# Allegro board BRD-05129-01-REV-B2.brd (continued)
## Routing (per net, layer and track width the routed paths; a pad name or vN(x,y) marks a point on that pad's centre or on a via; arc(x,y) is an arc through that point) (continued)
HPA09P: length 124.6
  TOP w0.094: JA1.D10 v4(12.65,46.94)
  L03_SIG w0.102: v1(103.93,78.84) 103.93,78.28 103.01,77.35 102.17,77.35 101.1,76.28 101.1,75.8 99.82,74.52 94.23,74.52 93.83,74.92 91.41,74.92 88.26,78.07 88.26,79.14 86.81,80.59 86.21,80.59 83.24,77.61 74.06,77.61 70.02,73.57 70.02,73.27 65.43,68.68 53.11,68.68 50.74,66.31 50.74,58.79 48.93,56.98 48.17,56.98 44.89,53.71 27.19,53.71 19.58,46.1 14.42,46.1 14.04,46.48 13.11,46.48 v4(12.65,46.94)
  BOTTOM w0.13: v1(103.93,78.84) 103.93,79.24 R584.1 103.47,80.17 103.37,80.26 102.76,80.26 102.59,80.43 R570.2 102.59,81.4 101.77,82.22 100.7,82.22 100.27,82.64 100.27,83.66 100.03,83.9 U99.30
HPA10_CCN: length 134.4
  TOP w0.094: JA1.C13 v3(14.34,49.39)
  L03_SIG w0.102: v1(19.58,50.59) 17.85,50.59 17.34,50.08 15.03,50.08 v3(14.34,49.39)
  L05_SIG w0.102: v1(31.52,50.59) v1(19.58,50.59)
  L12_SIG w0.102: v1(31.52,50.59) 31.52,49.81 31.64,49.68 34.84,49.68 34.97,49.81 34.97,51.63 34.82,51.77 33.16,51.77 33.02,51.92 33.02,52.13 33.16,52.28 34.82,52.28 34.97,52.43 34.97,53.73 36.46,55.22 36.75,55.22 38.32,56.8 38.32,58.95 39.47,60.09 39.47,61.87 43.24,65.64 50.27,65.64 51.05,66.42 64.49,66.42 72.99,74.92 89.21,74.92 90.2,73.93 95.22,73.93 95.98,74.69 95.98,75.26 96.31,75.59 99.89,75.59 101.11,74.37 104.62,74.37 106.93,76.68 106.93,84.3 106.55,84.68 105.41,84.68 v1(101.55,88.54)
  BOTTOM w0.13: R563.2 102.09,88.82 101.82,88.82 v1(101.55,88.54) 101.24,88.24 101.24,87.86 100.96,87.57 100.7,87.57 100.03,86.9 U99.24
HPA10_CCP_CLK: length 133.1
  TOP w0.094: v3(14.34,48.75) 14.29,48.76 JA1.C12
  L03_SIG w0.102: v1(77.83,86.22) 76.83,85.21 72.01,85.21 71.78,84.98 71.78,83.18 71.07,82.47 69,82.47 67.78,81.25 66.83,81.25 63.64,78.06 62.28,78.06 62.04,78.3 60.04,78.3 59.3,79.04 54.08,79.04 52.83,77.8 52.52,77.8 51.84,77.11 50.5,77.11 49.08,75.69 49.08,74.35 44.92,70.19 43.65,70.19 33.74,60.28 32.49,60.28 32.34,60.13 32.34,58.2 32.19,58.05 31.98,58.05 31.83,58.2 31.83,60.13 31.69,60.28 31.48,60.28 31.33,60.13 31.33,58.2 31.18,58.05 30.97,58.05 30.82,58.2 30.82,60.13 30.67,60.28 30.46,60.28 30.31,60.13 30.31,58.2 30.16,58.05 29.95,58.05 29.8,58.2 29.8,60.13 29.65,60.28 29.44,60.28 29.29,60.13 29.29,58.2 29.15,58.05 28.94,58.05 28.79,58.2 28.79,60.13 28.64,60.28 28.43,60.28 28.28,60.13 28.28,58.2 28.13,58.05 27.92,58.05 27.77,58.2 27.77,60.13 27.62,60.28 26.91,60.28 18.63,52 15.07,52 14.7,51.63 14.7,50.47 13.86,49.63 13.86,49.23 v3(14.34,48.75)
  L05_SIG w0.102: v1(77.83,86.22) 77.83,87.07 82.2,91.44 94.56,91.44 97,89 99.82,89 v1(100.76,88.06)
  BOTTOM w0.13: U99.23 100.1,87.4 100.57,87.88 100.58,87.88 v1(100.76,88.06)
HPA11N: length 28.7
  TOP w0.094: JA1.B11 v4(15.19,47.57)
  L10_SIG w0.102: v4(15.19,47.57) 15.67,48.06 18.64,48.06 27.91,38.79 29.32,38.79 31.01,37.11 35.38,37.11 v1(36.01,37.73)
  BOTTOM w0.13: U19.2 35.09,39.46 35.51,39.03 35.51,38.22 v1(36.01,37.73)
HPA11P_CLK: length 71.6
  TOP w0.094: JA1.B10 v4(15.19,46.94)
  L03_SIG w0.102: v4(15.19,46.94) 15.6,47.35 15.6,48 15.83,48.23 19.17,48.23 27.3,56.37 32.34,56.37 49.73,73.76 49.99,73.76 53.46,77.24 53.46,77.44 53.89,77.87 55.5,77.87 56.69,76.68 58.8,76.68 59.66,77.54 60.75,77.54 61.21,77.08 63.78,77.08 66.85,80.15 67.52,80.15 v1(69.2,81.83)
  BOTTOM w0.13: v1(69.2,81.83) R477.2
HPA11P_CLK_R: length 1.8
  BOTTOM w0.13: R477.1 U91.3
HPA12N: length 39.8
  TOP w0.094: JA1.A10 v4(16.93,47.53)
  L05_SIG w0.102: v4(16.93,47.53) 17.51,48.12 33.84,48.12 35.33,46.63 41.25,46.63 48.46,39.42 v1(50.16,39.42)
  BOTTOM w0.13: v1(50.16,39.42) 50.16,40.43 50.42,40.7 U115.13
HPA12P_CLK: length 38.8
  TOP w0.094: JA1.A9 v4(16.93,46.9)
  L05_SIG w0.102: v4(16.93,46.9) 30.74,46.9 31.58,46.06 40.22,46.06 46.27,40 v1(46.27,39.62)
  BOTTOM w0.13: v1(46.27,39.62) 48.14,41.49 50.54,41.49 50.55,41.5 U115.15
HPA13N: length 38.6
  TOP w0.094: JA1.A13 v4(16.83,49.39)
  L05_SIG w0.102: v1(49.21,40.62) 40.44,49.39 36.41,49.39 36.41,49.39 36.02,49.39 36.02,49.39 v4(16.83,49.39)
  BOTTOM w0.13: U115.14 50.56,41.1 50.55,41.11 49.69,41.11 v1(49.21,40.62)
HPA13P: length 39.6
  TOP w0.094: JA1.A12 v4(16.83,48.75)
  L05_SIG w0.102: v4(16.83,48.75) 33.89,48.75 34.55,48.09 40.67,48.09 48.74,40.03 50.83,40.03 v1(51.19,39.67)
  BOTTOM w0.13: U115.12 51.77,40.26 v1(51.19,39.67)
HPA14N: length 23.7
  TOP w0.094: JA1.D14 v4(12.65,49.48)
  L12_SIG w0.102: v4(12.65,49.48) 9.91,49.48 8.35,47.93 8.35,42.9 7.63,42.17 6.41,42.17 5.84,41.6 5.84,39.28 5.16,38.6 4.93,38.6 4.39,38.07 4.39,36.55 5.76,35.17 v1(5.76,34.59)
  BOTTOM w0.13: R474.1 5.45,34.9 v1(5.76,34.59) 5.35,34.18 Q23.1
HPA14P: length 18.1
  TOP w0.094: JA1.D13 v4(12.65,48.84)
  L12_SIG w0.102: v4(12.65,48.84) 9.95,48.84 8.99,47.88 8.99,42.52 8.36,41.88 8.36,41.01 v1(5.02,37.67)
  BOTTOM w0.13: v1(5.02,37.67) Q22.1 5.61,37.1 5.7,37.19 R473.1
HPA15_CCN: length 102.9
  TOP w0.127: v1(99.74,83.1) 99.54,83.3 U101.1
  TOP w0.13: JA3.C2 v4(45.17,58.28)
  L05_SIG w0.102: v1(99.74,83.1) 99.74,81.99 99.92,81.81 100.38,81.81 100.54,81.65 100.54,81.37 100.16,80.99 98.85,80.99 98.7,81.14 98.7,82.73 99.03,83.05 99.03,83.74 98.88,83.89 98.68,83.89 98.57,83.79 98.57,83.33 98.5,83.26 98.33,83.26 98.2,83.38 98.2,83.74 98.05,83.89 97.84,83.89 97.69,83.74 97.69,83.15 97.57,83.03 97.36,83.03 97.19,83.2 97.19,83.74 97.04,83.89 96.83,83.89 96.68,83.74 96.68,83.15 96.55,83.03 96.16,83.03 96.01,83.18 96.01,83.79 95.91,83.89 95.5,83.89 95.35,83.74 95.35,82.55 95.47,82.43 98.01,82.43 98.2,82.24 98.2,80.38 98.01,80.19 97.83,80.19 97.68,80.34 97.68,81.11 97.56,81.24 97.32,81.24 97.14,81.07 97.14,80.07 96.99,79.92 96.78,79.92 96.63,80.07 96.63,81.02 96.43,81.21 96.25,81.21 96.13,81.09 96.13,80.07 95.98,79.92 95.77,79.92 95.62,80.07 95.62,81.02 95.42,81.21 95.24,81.21 95.11,81.09 95.11,80.07 94.96,79.92 94.75,79.92 94.6,80.07 94.6,81.02 94.4,81.21 94.22,81.21 94.09,81.09 94.09,80.07 93.95,79.92 93.73,79.92 93.59,80.07 93.59,80.91 93.44,81.06 92.07,81.06 91.67,80.66 91.02,80.66 89.55,79.19 89.15,79.19 88.97,79.37 88.74,79.37 88.64,79.27 88.64,78.96 88.53,78.85 88.3,78.85 88.17,78.98 88.17,79.86 87.97,80.07 87.74,80.07 87.61,79.94 87.61,79.74 87.46,79.6 87.14,79.6 86.98,79.43 86.98,78.27 86.85,78.15 78.18,78.15 78,78.33 74.55,78.33 70.02,73.8 70.02,72.12 66.88,68.98 61.68,68.98 61.14,68.44 51.61,68.44 49.94,66.76 49.94,60.29 48.93,59.28 47.56,59.28 47.32,59.04 47.32,57.97 47.21,57.87 45.59,57.87 v4(45.17,58.28)
HPA15_CCP: length 104.9
  TOP w0.127: v1(100.63,76.09) 99.78,76.95 99.78,81.22 98.44,82.55 U101.39
  TOP w0.13: JA3.C1 v4(44.35,57.07)
  L05_SIG w0.102: v1(100.63,76.09) 100.63,75.38 99.77,74.52 93.09,74.52 91.77,75.84 91.08,75.84 90.93,75.69 90.93,75.13 90.78,74.98 90.57,74.98 90.42,75.13 90.42,75.69 90.27,75.84 90.06,75.84 89.91,75.69 89.91,75.13 89.76,74.98 89.55,74.98 89.4,75.13 89.4,75.69 89.25,75.84 89.04,75.84 88.9,75.69 88.9,75.13 88.75,74.98 88.54,74.98 88.39,75.13 88.39,75.69 88.24,75.84 88.03,75.84 87.88,75.69 87.88,75.13 87.73,74.98 87.52,74.98 87.37,75.13 87.37,75.69 87.22,75.84 87.01,75.84 86.86,75.69 86.86,75.13 86.71,74.98 86.5,74.98 86.36,75.13 86.36,75.69 86.21,75.84 86,75.84 85.85,75.69 85.85,75.13 85.7,74.98 85.49,74.98 85.34,75.13 85.34,75.69 85.19,75.84 84.98,75.84 84.83,75.69 84.83,75.13 84.68,74.98 84.47,74.98 84.32,75.13 84.32,75.69 84.17,75.84 83.96,75.84 83.82,75.69 83.82,75.13 83.67,74.98 83.46,74.98 83.31,75.13 83.31,75.69 83.16,75.84 82.95,75.84 82.8,75.69 82.8,75.13 82.65,74.98 82.44,74.98 82.29,75.13 82.29,75.69 82.14,75.84 81.93,75.84 81.78,75.69 81.78,75.13 81.63,74.98 81.42,74.98 81.28,75.13 81.28,75.69 81.13,75.84 80.92,75.84 80.77,75.69 80.77,75.13 80.62,74.98 80.41,74.98 80.26,75.13 80.26,75.69 80.11,75.84 79.9,75.84 79.75,75.69 79.75,75.13 79.6,74.98 79.39,74.98 79.24,75.13 79.24,75.69 79.09,75.84 78.88,75.84 78.74,75.69 78.74,75.13 78.59,74.98 78.38,74.98 78.23,75.13 78.23,75.69 78.08,75.84 77.87,75.84 77.72,75.69 77.72,75.13 77.57,74.98 77.36,74.98 77.21,75.13 77.21,75.69 77.06,75.84 76.85,75.84 76.7,75.69 76.7,75.13 76.55,74.98 76.34,74.98 76.2,75.13 76.2,75.69 76.05,75.84 75.69,75.84 72.72,72.86 72.72,70.62 68.12,66.03 53.95,66.03 53.02,65.1 53.02,59.7 49.65,56.34 49.65,54.91 48.87,54.12 44.6,54.12 43.58,55.14 43.58,56.31 v4(44.35,57.07)
HPA16N: length 103.9
  TOP w0.127: v1(98.22,75.08) 98.85,75.71 98.85,81.25 97.44,82.66 U101.37
  TOP w0.13: JA3.A2 v4(47.71,58.28)
  L05_SIG w0.102: v1(98.22,75.08) 98.73,75.59 98.73,76.07 98.88,76.22 98.96,76.22 99.11,76.37 99.11,76.58 98.96,76.73 98.88,76.73 98.73,76.88 98.73,77.32 98.88,77.47 99.69,77.47 99.9,77.27 100.11,77.27 100.25,77.42 100.25,77.63 100.05,77.83 100.05,78.04 100.32,78.3 103.2,78.3 103.65,77.85 104.22,77.85 104.77,78.41 108.1,78.41 108.23,78.53 108.23,78.84 108.16,79.01 108.05,79.12 104.42,79.12 104.11,79.42 102.97,79.42 102.82,79.57 102.82,80.41 102.67,80.56 102.46,80.56 102.31,80.41 102.31,78.94 102.19,78.82 101.92,78.82 101.82,78.91 101.82,79.32 101.72,79.42 101.29,79.42 100.78,79.93 100.5,79.93 99.93,79.36 99.93,79.19 100.08,79.04 100.08,78.87 99.96,78.75 99.79,78.75 99.64,78.9 99.47,78.9 99.01,78.44 98.78,78.44 98.65,78.31 98.65,77.97 98.5,77.82 98.24,77.82 98.04,78.02 98.04,78.3 97.91,78.44 94.11,78.44 93.56,77.89 91.1,77.89 90.07,76.86 77.61,76.86 77.11,77.36 75.17,77.36 71.27,73.46 71.27,71.35 67.39,67.48 53.17,67.48 51.47,65.77 51.47,60.29 48.94,57.76 47.84,57.76 47.71,57.88 v4(47.71,58.28)
HPA16P_CLK: length 105.1
  TOP w0.127: v4(48.74,58.24) 48.74,57.83 48.28,57.37 JA3.A1 ; U101.38 97.94,82.59 99.31,81.22 99.31,76.39 v1(99.61,76.09)
  L05_SIG w0.102: v4(48.74,58.24) 50.65,60.15 50.65,65.86 52.75,67.96 61.5,67.96 61.84,68.3 67.14,68.3 70.62,71.78 70.62,73.56 74.9,77.85 77.4,77.85 77.76,77.48 87.83,77.48 87.98,77.63 87.98,78.22 88.13,78.37 88.34,78.37 88.49,78.22 88.49,77.63 88.64,77.48 89.07,77.48 90.74,79.15 92.53,79.15 92.76,78.93 98.78,78.93 99.11,79.25 99.11,79.46 98.63,79.94 98.63,80.15 98.78,80.3 98.99,80.3 99.47,79.82 99.68,79.82 100.89,81.04 103.31,81.04 103.73,80.62 105.24,80.62 105.39,80.47 105.39,79.75 105.54,79.6 105.75,79.6 105.9,79.75 105.9,80.47 106.05,80.62 106.26,80.62 106.41,80.47 106.41,79.75 106.55,79.6 106.76,79.6 106.91,79.75 106.91,80.47 107.06,80.62 107.27,80.62 107.42,80.47 107.42,79.75 107.57,79.6 107.78,79.6 107.93,79.75 107.93,80.65 108.15,80.87 108.42,80.87 108.71,80.59 108.71,78.25 108.38,77.92 104.97,77.92 104.4,77.35 101.96,77.35 101.21,76.6 100.12,76.6 v1(99.61,76.09)
HPA17N: length 101.8
  TOP w0.127: U101.35 96.44,82.19 97.2,81.43 R597.2 97.71,80.51 97.71,79.21 R608.1 96.86,78.7 96.69,78.53 96.69,76.6 v1(97.2,76.09)
  TOP w0.13: JA3.D3 v4(43.53,58.37)
  L05_SIG w0.102: v1(97.2,76.09) 97.67,76.56 97.67,77.64 97.42,77.89 95.9,77.89 95.69,77.68 95.69,76.29 95.54,76.14 94.94,76.14 94.67,76.41 94.67,77.76 94.54,77.89 94.25,77.89 93.66,77.31 91.78,77.31 91.5,77.03 91.5,76.65 91.2,76.35 75.52,76.35 72.23,73.06 72.23,70.82 67.92,66.51 53.57,66.51 52.44,65.37 52.44,59.8 48.48,55.85 48.13,55.85 47.38,56.6 46.93,56.6 46.79,56.45 46.79,55.01 46.62,54.85 44.84,54.85 44.41,55.27 44.41,56.24 44.83,56.65 44.83,57.15 44.37,57.6 43.28,57.6 43.1,57.43 43.1,53.64 42.92,53.46 42.41,53.46 42.26,53.62 42.26,57.48 42.13,57.6 40.33,57.6 40.2,57.73 40.2,58.14 40.44,58.37 v4(43.53,58.37)
HPA17P: length 87.4
  TOP w0.127: Q33.1 80.53,96.67 R596.1 v1(81.33,96.57) ; U101.21 93.84,88.82 93.39,89.28 93.18,89.28 92.66,89.81 92.66,90.01 92.07,90.59 91.43,90.59 91.05,90.97 R605.2 R616.1 v1(91.05,92.63)
  TOP w0.13: JA3.D2 v4(44.36,58.3) ; v1(81.33,96.57) 81.33,96.13 81.96,95.5 81.96,92.71 79,89.75 79,79.36 v1(76.53,76.88)
  L05_SIG w0.102: v4(44.36,58.3) 45.18,57.48 46.25,57.48 46.48,57.25 49.17,57.25 51.95,60.03 51.95,65.57 53.37,66.99 67.72,66.99 71.75,71.02 71.75,73.26 75.37,76.88 v1(76.53,76.88)
  L10_SIG w0.102: v1(91.05,92.63) 90.39,91.97 87.35,91.97 82.75,96.57 v1(81.33,96.57)
HPA18N: length 99
  TOP w0.13: JA3.B3 v4(46.07,58.37) ; v1(93.14,78.38) 93.46,78.7 R611.1 93.65,79.21 93.65,80.82 93.82,80.99 R600.2 94.15,81.96 94.94,82.75 U101.32
  L03_SIG w0.102: v4(46.07,58.37) 46.45,58.75 46.45,59.36 46.71,59.61 47.09,59.61 47.32,59.84 47.32,61.06 48.27,62.01 48.27,65.33 48.12,65.48 47.76,65.48 47.61,65.63 47.61,65.84 47.76,65.99 48.12,65.99 48.27,66.14 48.27,66.35 48.12,66.5 47.76,66.5 47.61,66.64 47.61,66.86 47.76,67 48.12,67 48.27,67.15 48.27,67.82 51.79,71.34 51.79,72 52.78,73 54.45,73 55.24,72.21 56.65,72.21 56.79,72.36 56.79,73.53 56.94,73.68 57.15,73.68 57.3,73.53 57.3,72.36 57.45,72.21 57.66,72.21 57.81,72.36 57.81,73.53 57.96,73.68 58.17,73.68 58.32,73.53 58.32,72.36 58.47,72.21 60.25,72.21 60.4,72.36 60.4,72.92 60.55,73.07 60.76,73.07 60.91,72.92 60.91,72.36 61.06,72.21 61.27,72.21 61.42,72.36 61.42,72.92 61.57,73.07 61.78,73.07 61.92,72.92 61.92,72.36 62.07,72.21 62.28,72.21 62.43,72.36 62.43,72.92 62.58,73.07 62.79,73.07 62.94,72.92 62.94,72.36 63.09,72.21 63.64,72.21 65.33,73.91 66.71,73.91 72.83,80.03 74.75,80.03 77.21,82.49 88.28,82.49 88.81,81.96 90.24,81.96 91.05,82.78 92.86,82.78 94.5,84.42 94.5,86.48 94.75,86.73 94.9,86.73 95.09,86.54 95.09,84.69 95.34,84.44 96.01,84.44 96.11,84.34 96.11,83.61 96.01,83.5 94.88,83.5 94.61,83.24 94.61,82.44 93.46,81.29 92.25,81.29 91.91,80.95 91.91,80.3 92.53,79.68 92.53,78.99 v1(93.14,78.38)
HPA18P: length 99
  TOP w0.13: v1(94.15,76.09) 94.67,76.61 94.67,78.58 94.8,78.7 R612.1 94.66,79.21 94.66,80.82 94.83,80.99 R603.2 95.4,81.22 95.4,82.59 95.44,82.64 U101.33 ; JA3.B2 v4(46.9,58.3)
  L03_SIG w0.102: v1(94.15,76.09) 93.62,76.09 93.39,76.32 93.39,76.68 93.62,76.92 93.62,77.13 93.48,77.28 93.27,77.28 93.03,77.04 92.82,77.04 92.56,77.31 91.49,77.31 89.8,79 89.8,79.87 89.17,80.5 88.91,80.5 87.9,81.5 85.52,81.5 84.89,80.88 83.36,80.88 83.21,80.73 83.21,79.18 83.11,79.08 82.8,79.08 82.7,79.18 82.7,80.73 82.55,80.88 82.34,80.88 82.19,80.73 82.19,78.98 82.02,78.8 81.81,78.8 81.69,78.93 81.69,80.73 81.54,80.88 80.47,80.88 80.32,80.73 80.32,79.01 80.15,78.84 79.94,78.84 79.81,78.96 79.81,80.73 79.66,80.88 79.31,80.88 79.14,80.72 79.14,78.95 78.91,78.71 72.89,78.71 68.39,74.21 68.39,73.25 68.13,72.99 67.92,72.99 67.55,73.36 67.33,73.36 67.19,73.21 67.19,73 67.56,72.63 67.56,72.42 67.01,71.87 66.72,71.87 66.57,71.72 66.57,71.52 66.42,71.37 66.21,71.37 66.06,71.52 66.06,71.72 65.91,71.87 65.57,71.87 65.2,71.49 65.2,71.28 65.7,70.78 65.7,70.57 65.55,70.42 65.34,70.42 64.71,71.05 64.47,71.05 64.32,70.9 64.32,70.72 64.98,70.06 64.98,69.85 64.83,69.71 64.62,69.71 64.12,70.21 63.91,70.21 63.52,69.82 62.87,69.82 62.72,69.97 62.72,70.48 62.58,70.63 62.37,70.63 62.22,70.48 62.22,69.97 62.07,69.82 61.86,69.82 61.71,69.97 61.71,70.48 61.56,70.63 61.35,70.63 61.2,70.48 61.2,69.97 61.05,69.82 60.84,69.82 60.69,69.97 60.69,70.48 60.54,70.63 60.33,70.63 60.18,70.48 60.18,69.97 60.04,69.82 58.7,69.82 58.55,69.97 58.55,70.67 58.39,70.84 58.18,70.84 58.04,70.7 58.04,69.97 57.9,69.82 57.43,69.82 57.07,70.18 54.64,70.18 54.25,70.57 52.87,70.57 49.61,67.3 49.61,60.4 48.12,58.91 48.12,57.97 47.95,57.81 47.39,57.81 v4(46.9,58.3)
HPA19N: length 104.2
  TOP w0.127: U101.29 93.37,84.4 93.06,84.09 93.06,83.15 92.05,82.14 92.05,81.76 v1(91.74,81.45) R609.1 R598.2
  TOP w0.13: JA3.C5 v4(45.17,60.18)
  L05_SIG w0.102: v4(45.17,60.18) 44.8,59.81 42.92,59.81 42.8,59.69 42.8,59.46 42.87,59.38 45.64,59.38 45.77,59.51 48.1,59.51 49.26,60.67 49.26,66.77 51.41,68.92 54.43,68.92 54.57,69.07 54.57,69.44 54.72,69.59 54.93,69.59 55.08,69.44 55.08,69.07 55.23,68.92 56.64,68.92 56.79,69.07 56.79,69.47 56.93,69.62 57.14,69.62 57.29,69.47 57.29,69.07 57.44,68.92 59.51,68.92 59.51,68.93 60.81,68.93 61.44,69.56 66.62,69.56 69.53,72.47 69.53,74.67 69.78,74.91 69.99,74.91 70.11,74.79 70.32,74.79 70.47,74.94 70.47,75.15 70.35,75.27 70.35,75.48 70.49,75.63 70.7,75.63 70.83,75.51 71.04,75.51 71.19,75.65 71.19,75.86 71.06,75.99 71.06,76.2 71.21,76.35 71.42,76.35 71.55,76.22 71.76,76.22 71.91,76.37 71.91,76.58 71.78,76.71 71.78,76.92 71.93,77.07 72.14,77.07 72.27,76.94 72.48,76.94 72.62,77.09 72.62,77.3 72.5,77.42 72.5,77.64 72.65,77.78 72.86,77.78 72.98,77.66 73.19,77.66 73.34,77.81 73.34,78.02 73.22,78.14 73.22,78.35 73.68,78.81 77.51,78.81 77.66,78.96 77.66,80.21 77.81,80.36 78.02,80.36 78.17,80.21 78.17,78.96 78.32,78.81 80.19,78.81 80.32,78.68 81.68,78.68 81.83,78.83 81.83,78.97 81.97,79.12 82.18,79.12 82.33,78.97 82.33,78.83 82.48,78.68 82.69,78.68 82.84,78.83 82.84,78.97 82.99,79.12 83.2,79.12 83.35,78.97 83.35,78.83 83.5,78.68 83.71,78.68 83.86,78.83 83.86,78.97 84.01,79.12 84.22,79.12 84.37,78.97 84.37,78.83 84.51,78.68 85.03,78.68 85.8,79.46 85.8,80.22 86.13,80.55 86.82,80.55 86.96,80.7 86.96,81.69 87.11,81.84 87.32,81.84 87.47,81.69 87.47,80.7 87.62,80.55 87.83,80.55 87.98,80.7 87.98,81.69 88.13,81.84 88.34,81.84 88.49,81.69 88.49,80.7 88.64,80.55 89.16,80.55 89.56,80.96 89.77,80.96 90.09,80.63 90.3,80.63 90.45,80.78 90.45,80.99 90.13,81.31 90.13,81.52 90.28,81.67 90.49,81.67 90.81,81.35 91.02,81.35 91.17,81.5 91.17,81.71 90.85,82.03 90.85,82.24 91.1,82.49 91.31,82.49 91.59,82.2 91.8,82.2 91.95,82.35 91.95,82.56 91.66,82.85 91.66,83.06 91.89,83.29 91.89,83.76 92.23,84.1 92.66,84.1 93.51,84.95 94.13,84.95 94.64,84.44 94.64,84.03 94.49,83.88 93.38,83.88 93.23,83.73 93.23,83.52 93.38,83.37 94.49,83.37 94.64,83.22 94.64,82.37 94.14,81.88 93.43,81.88 93.28,82.03 93.28,82.78 93.13,82.93 92.92,82.93 92.77,82.78 92.77,82.03 92.62,81.88 92.16,81.88 v1(91.74,81.45)
HPA19P: length 104.4
  TOP w0.127: U101.30 93.61,83.9 93.39,83.69 93.39,82.83 92.43,81.86 92.43,80.62 v1(92.38,80.56) R610.1 R599.2
  TOP w0.13: JA3.C4 v4(44.35,58.98)
  L03_SIG w0.102: v4(44.35,58.98) 44.96,59.58 46.15,59.58 46.5,59.94 46.5,61.11 47.32,61.92 47.32,62.99 47.11,63.19 43.56,63.19 43.3,63.44 43.3,64.94 52.17,73.81 55.22,73.81 56.31,74.9 60.19,74.9 61.33,73.76 64.34,73.76 65.05,74.47 66.46,74.47 67,75.01 67,75.22 66.29,75.93 66.29,76.14 66.44,76.29 66.65,76.29 67.36,75.58 67.57,75.58 68.26,76.27 68.26,76.48 67.58,77.15 67.58,77.36 67.73,77.51 67.94,77.51 68.61,76.84 68.83,76.84 68.97,76.99 68.97,77.2 68.3,77.87 68.3,78.08 68.45,78.23 68.66,78.23 69.33,77.56 69.54,77.56 69.69,77.71 69.69,77.92 69.02,78.59 69.02,78.8 69.17,78.95 69.38,78.95 70.05,78.28 70.26,78.28 72.5,80.51 74.42,80.51 76.89,82.97 89.95,82.97 91.14,84.16 92.78,84.16 93.98,85.36 93.98,86.72 95.2,87.94 97.89,87.94 98.37,87.47 98.37,84.59 95.55,81.77 95.55,81.48 94.64,80.56 v1(92.38,80.56)
HPA20_CCN_NC: length 0.4
  TOP w0.13: JA3.A5 v4(47.71,60.18)
HPA20_CCP_CLK: length 88.2
  TOP w0.127: U101.34 95.94,82.3 95.7,82.06 95.7,81.47 R601.2 96.45,80.99 96.47,80.97 96.57,80.97 96.69,80.84 96.69,79.21 R614.1 95.8,78.7 95.68,78.58 95.68,76.6 v1(96.19,76.09)
  TOP w0.13: JA3.A4 v4(46.89,58.98)
  L03_SIG w0.102: v4(46.89,58.98) 47.27,59.36 47.7,59.36 48.9,60.56 48.9,67.69 52.84,71.62 59.09,71.62 59.58,71.13 63.74,71.13 64.96,72.35 65.85,72.35 68.65,75.15 68.65,75.17 72.8,79.32 76.33,79.32 78.72,81.71 84.59,81.71 84.87,81.99 88.1,81.99 89.11,80.98 89.54,80.98 90.73,79.8 90.73,79.03 91.86,77.9 93.75,77.9 94.41,78.56 98.51,78.56 98.88,78.93 98.88,80.71 99.01,80.84 99.61,80.84 99.74,80.71 99.74,78.51 99.05,77.83 96.8,77.83 96.67,77.7 96.67,76.58 v1(96.19,76.09)
HPA21N_NC: length 0.4
  TOP w0.13: JA3.D6 v4(43.53,60.27)
HPA21P_CLK: length 55.9
  TOP w0.13: JA3.D5 v4(44.36,60.21)
  L05_SIG w0.102: v4(44.36,60.21) 43.96,60.61 43.96,61.14 44.78,61.96 44.78,62.93 44.21,63.5 44.21,66.91 50.07,72.76 51.16,72.76 52.59,74.2 55.65,74.2 56.23,74.77 62.13,74.77 62.76,74.14 65.43,74.14 66.62,75.33 66.62,76.7 72.29,82.37 74.21,82.37 77.22,85.39 v1(78.05,85.39)
  BOTTOM w0.13: R479.2 80.01,83.43 v1(78.05,85.39)
HPA21P_CLK_R: length 1.7
  BOTTOM w0.13: R479.1 79.11,81.24 78.72,81.63 U91.5
HPA22N: length 91.4
  TOP w0.127: v1(88.74,88.34) 89.11,88.7 90.92,88.7 91.05,88.83 R592.2 91.49,89.2 91.64,89.05 91.64,88.37 91.92,88.08 92.36,88.08 92.45,87.99 92.45,87.75 93.24,86.97 93.78,86.97 U101.24
  TOP w0.13: JA3.B6 v4(46.07,60.27)
  L05_SIG w0.102: v1(88.74,88.34) 88.41,88.67 87.34,88.67 87.21,88.54 87.21,85.55 84.55,82.89 80.78,82.89 80.66,83.01 80.66,83.72 80.55,83.84 80.38,83.84 80.26,83.72 80.26,83.01 80.14,82.89 79.97,82.89 79.85,83.01 79.85,83.72 79.73,83.84 79.56,83.84 79.45,83.72 79.45,83.01 79.33,82.89 79.16,82.89 79.04,83.01 79.04,83.72 78.92,83.84 78.75,83.84 78.63,83.72 78.63,83.01 78.51,82.89 78.35,82.89 78.23,83.01 78.23,83.72 78.11,83.84 77.94,83.84 77.82,83.72 77.82,83.01 77.7,82.89 77.53,82.89 77.41,83.01 77.41,83.85 77.29,83.97 77.13,83.97 77.01,83.85 77.01,83.01 76.89,82.89 76.4,82.89 74.95,81.45 73.53,81.45 65.35,73.27 64.7,73.27 64.58,73.16 64.58,71.95 64.46,71.83 64.29,71.83 64.17,71.95 64.17,73.16 64.06,73.27 63.89,73.27 63.77,73.16 63.77,71.95 63.65,71.83 63.48,71.83 63.36,71.95 63.36,73.16 63.24,73.27 63.07,73.27 62.96,73.16 62.96,71.95 62.84,71.83 62.67,71.83 62.55,71.95 62.55,73.16 62.43,73.27 62.26,73.27 62.14,73.16 62.14,71.95 62.02,71.83 61.85,71.83 61.74,71.95 61.74,73.16 61.62,73.27 59.97,73.27 59.61,73.63 59.16,73.63 59.01,73.49 59.01,72.94 58.89,72.82 58.64,72.82 58.5,72.95 58.5,73.49 58.36,73.63 58.15,73.63 58,73.49 58,72.9 57.87,72.78 57.66,72.78 57.49,72.95 57.49,73.49 57.34,73.63 52.71,73.63 51.36,72.28 50.42,72.28 44.87,66.73 44.87,63.54 45.29,63.12 45.39,63.12 45.6,62.9 45.6,60.39 45.72,60.27 v4(46.07,60.27)
HPA22P: length 90.8
  TOP w0.127: U101.23 93.23,87.4 92.76,87.88 92.76,88.69 v1(91.87,89.58)
  TOP w0.13: JA3.B5 v4(46.9,60.21)
  L05_SIG w0.102: v4(46.9,60.21) 47.32,59.78 47.91,59.78 48.51,60.39 48.51,66.71 51.21,69.41 53.56,69.41 54.25,70.1 57.85,70.1 58.54,69.41 60.41,69.41 61.12,70.12 66.4,70.12 68.39,72.11 68.39,74.21 73.48,79.29 74.85,79.29 75.86,80.31 76.77,80.31 77.5,81.04 78.66,81.04 78.81,80.89 78.81,79.87 78.96,79.73 79.17,79.73 79.32,79.87 79.32,80.89 79.47,81.04 79.68,81.04 79.83,80.89 79.83,79.87 79.98,79.73 80.19,79.73 80.34,79.87 80.34,80.89 80.48,81.04 81.48,81.04 81.63,80.89 81.63,79.8 81.77,79.65 81.98,79.65 82.13,79.8 82.13,80.89 82.28,81.04 82.49,81.04 82.64,80.89 82.64,79.8 82.79,79.65 83,79.65 83.15,79.8 83.15,80.89 83.3,81.04 83.51,81.04 83.66,80.89 83.66,79.8 83.81,79.65 84.02,79.65 84.17,79.8 84.17,80.89 84.31,81.04 84.52,81.04 84.67,80.89 84.67,79.8 84.82,79.65 85.03,79.65 85.18,79.8 85.18,80.89 87.31,83.02 88.05,83.02 88.2,82.87 88.2,82.51 88.35,82.36 88.56,82.36 88.71,82.51 88.71,82.87 88.86,83.02 89.52,83.02 89.73,83.23 89.94,83.23 90.42,82.75 90.61,82.75 90.76,82.9 90.76,83.13 90.3,83.58 90.3,83.8 90.45,83.94 90.66,83.94 90.97,83.63 91.18,83.63 91.33,83.78 91.33,83.99 91.02,84.3 91.02,84.51 91.18,84.68 91.18,87.57 91.36,87.75 93.6,87.75 93.75,87.91 93.75,88.79 93.52,89.03 92.42,89.03 v1(91.87,89.58)
HPA23N: length 75.5
  TOP w0.13: JA3.C8 v4(45.17,62.09)
  L10_SIG w0.102: v1(83.12,17) 83.65,17.53 83.65,19.08 81.4,21.33 79.5,21.33 77.8,23.03 70.54,23.03 69.47,24.1 69.47,25.93 64.63,30.77 60.56,30.77 59.46,31.87 56.54,31.87 54.72,33.69 54.72,36.68 56.09,38.05 56.09,47.94 55.44,48.58 55.44,56.18 50.19,61.44 45.82,61.44 v4(45.17,62.09)
  BOTTOM w0.13: U118.4 v1(83.12,17)
HPA23P_CLK: length 75.6
  TOP w0.13: JA3.C7 v4(44.35,60.88)
  L10_SIG w0.102: v4(44.35,60.88) 44.76,60.47 44.76,59.84 45.02,59.58 50.49,59.58 54.38,55.69 54.38,46.43 55.37,45.44 55.37,38.78 53.21,36.62 53.21,27.76 55.62,25.34 65.48,25.34 67.06,23.76 67.06,22.7 68.84,20.93 71.67,20.93 72.46,21.71 77.09,21.71 78.81,19.99 v1(78.81,18.18)
  BOTTOM w0.13: v1(78.81,18.18) 78.81,17.72 79.26,17.28 U120.5
HPA24N: length 90.9
  TOP w0.127: v1(100.76,82.85) 100.76,84.12 99.98,84.9 U101.3
  TOP w0.13: JA3.A8 v4(47.71,62.09)
  L05_SIG w0.102: v4(47.71,62.09) 48.09,62.46 48.09,63.11 48.03,63.18 48.03,66.9 51.58,70.46 53.54,70.46 54.39,71.3 57.36,71.3 58.77,69.89 60.21,69.89 60.92,70.6 66.11,70.6 67.45,71.95 67.45,73.95 73.28,79.78 74.64,79.78 76.54,81.67 84.84,81.67 87.19,84.02 89.58,84.02 90.57,85.01 90.57,85.3 90.42,85.45 89.98,85.45 89.84,85.6 89.84,85.81 89.98,85.96 90.42,85.96 90.57,86.11 90.57,86.32 90.42,86.46 89.98,86.46 89.84,86.61 89.84,86.82 89.98,86.97 90.42,86.97 90.57,87.12 90.57,88.97 91.67,90.06 92.07,90.06 92.62,89.51 94.08,89.51 94.23,89.36 94.23,86.86 94.38,86.71 94.59,86.71 94.74,86.86 94.74,89.36 94.89,89.51 95.12,89.51 96.77,87.85 98.04,87.85 98.93,86.96 98.93,86.75 98.34,86.16 98.34,85.95 98.49,85.8 98.7,85.8 99.29,86.39 100.06,86.39 100.25,86.2 100.25,85.51 100.1,85.36 99.44,85.36 99.29,85.21 99.29,85 99.44,84.85 100.1,84.85 100.25,84.7 100.25,84.2 100.76,83.69 v1(100.76,82.85)
HPA24P: length 93.5
  TOP w0.127: U101.2 99.99,84.4 100.28,84.12 100.28,82.65 100.69,82.24 104.44,82.24 v1(104.92,82.72)
  TOP w0.13: JA3.A7 v4(46.89,60.88)
  L05_SIG w0.102: v4(46.89,60.88) 47.32,61.31 47.32,63.03 47.04,63.31 46.54,63.31 45.83,64.02 45.83,65.39 52.23,71.78 58.71,71.78 59.36,71.13 64.69,71.13 66.45,72.89 66.45,73.63 73.08,80.26 74.44,80.26 76.6,82.41 84.78,82.41 88.55,86.18 88.55,86.95 89.14,87.54 89.59,87.54 89.88,87.82 89.88,89.08 91.35,90.55 94.76,90.55 96.82,88.49 98.75,88.49 100.78,86.46 102.23,86.46 102.46,86.23 102.46,84.63 102.67,84.42 103.17,84.42 103.3,84.54 103.3,85.92 103.5,86.13 104.77,86.13 104.92,85.97 v1(104.92,82.72)
HPA25: length 75.2
  TOP w0.13: JA3.D8 v4(44.36,62.11)
  L12_SIG w0.102: v1(78.81,16.88) 79.28,17.35 79.28,21.57 79.42,21.71 79.42,27.43 76.09,30.76 63.17,30.76 61.42,32.5 56.49,32.5 52.9,36.1 52.9,37.38 51.7,38.57 51.7,40.14 51.14,40.71 50.49,40.71 49.22,41.98 49.22,44.6 48.47,45.35 48.47,55.81 49.42,56.76 49.42,60.7 48.71,61.41 44.7,61.41 44.36,61.76 v4(44.36,62.11)
  BOTTOM w0.13: U120.4 v1(78.81,16.88)
HPA26: length 81.8
  TOP w0.127: JA3.D9 v4(43.53,62.18)
  L10_SIG w0.102: v1(83.13,17.83) 82.8,17.5 78.49,17.5 78.08,17.91 78.08,19.41 77.36,20.14 67.9,20.14 64.14,23.9 55.47,23.9 52.42,26.95 52.42,37.52 54.15,39.25 54.15,40.25 53.49,40.91 53.49,54.81 50.54,57.76 43.61,57.76 42.97,58.39 42.97,61.62 v4(43.53,62.18)
  BOTTOM w0.13: U118.5 83.57,17.4 v1(83.13,17.83)
HPA27: length 90
  TOP w0.127: R602.2 R615.1 91.54,87.17 v1(91.74,86.97) 91.74,86.66 92.5,85.9 U101.26 ; Q34.1 v1(106.12,82.69)
  TOP w0.13: JA3.B8 v4(46.9,62.11)
  L03_SIG w0.102: v1(91.74,86.97) 91.54,86.97 90,85.43 87.77,85.43 86.71,84.37 81.82,84.37 81.64,84.2 76.33,84.2 74.24,82.11 73.22,82.11 70.75,79.64 68.57,79.64 66.09,77.16 65.44,77.16 64.43,76.15 64.43,74.59 64.12,74.28 61.67,74.28 60.57,75.39 56.03,75.39 55.12,74.48 52.16,74.48 42.75,65.07 42.75,62.07 43.18,61.64 46.42,61.64 v4(46.9,62.11)
  L05_SIG w0.102: v1(106.12,82.69) 105.61,82.18 100.69,82.18 100.25,82.62 100.25,83.28 99.15,84.37 95.54,84.37 92.75,87.17 91.94,87.17 v1(91.74,86.97)
HPA28: length 36.3
  TOP w0.13: JA3.B9 v4(46.07,62.18)
  L12_SIG w0.102: v4(46.07,62.18) 45.6,62.65 45.6,62.9 45.21,63.3 43.45,63.3 42.83,62.68 42.83,41.35 39.73,38.26 35.51,38.26 v1(34.99,38.78)
  BOTTOM w0.13: U19.3 34.69,39.08 v1(34.99,38.78)
HPA_CLK0N: length 133.9
  TOP w0.094: JA1.A7 v4(16.83,45.58)
  L10_SIG w0.102: v4(16.83,45.58) 19.61,45.58 27.48,37.71 29.56,37.71 v1(29.59,37.69)
  L12_SIG w0.102: v1(29.59,37.69) 32.45,37.69 35.17,40.41 39.68,40.41 41.4,42.13 41.4,46.99 41.25,47.14 40.15,47.14 40.01,47.29 40.01,47.5 40.15,47.64 41.25,47.64 41.4,47.79 41.4,48 41.25,48.15 40.15,48.15 40.01,48.3 40.01,48.51 40.15,48.66 41.25,48.66 41.4,48.81 41.4,49.02 41.25,49.17 40.15,49.17 40.01,49.32 40.01,49.53 40.15,49.68 41.25,49.68 41.4,49.83 41.4,50.04 41.25,50.18 40.15,50.18 40.01,50.33 40.01,50.54 40.15,50.69 41.25,50.69 41.4,50.84 41.4,51.05 41.25,51.2 40.15,51.2 40.01,51.35 40.01,51.56 40.15,51.71 41.25,51.71 41.4,51.86 41.4,55.23 41.76,55.59 41.76,62.77 43.01,64.02 45.52,64.02 46.21,63.33 49.87,63.33 52.36,65.82 64.98,65.82 72.9,73.74 76.14,73.74 76.57,74.16 89.28,74.16 90.02,73.43 95.63,73.43 96.7,74.5 v1(96.7,75.08)
  BOTTOM w0.13: v1(96.7,75.08) 96.7,78.29 97.12,78.7 R582.1 96.7,79.2 96.7,80.85 96.84,80.99 R568.2 97.2,81.5 97.2,81.51 97.2,81.91 97.2,81.91 97.2,82.15 96.94,82.41 U99.35
HPA_CLK0P_CLK: length 132.6
  TOP w0.094: JA1.A6 v4(16.83,44.94)
  L12_SIG w0.102: v1(98.22,76.09) 97.69,76.62 95.96,76.62 95.29,75.95 95.29,74.9 94.94,74.55 90.61,74.55 89.72,75.44 72.45,75.44 64.21,67.2 50.05,67.2 49.09,66.24 42.47,66.24 37.56,61.33 37.56,61.12 37.99,60.69 37.99,60.48 37.84,60.34 37.63,60.34 37.2,60.76 36.99,60.76 36.84,60.61 36.84,60.4 37.27,59.98 37.27,59.77 37.12,59.62 36.91,59.62 36.48,60.05 36.27,60.05 35.96,59.74 35.96,58.45 34.98,57.46 34.98,57.25 35.73,56.5 35.73,56.29 35.58,56.14 35.37,56.14 34.62,56.89 34.41,56.89 34.26,56.74 34.26,56.53 35.01,55.78 35.01,55.57 34.86,55.42 34.65,55.42 33.9,56.17 33.69,56.17 33.54,56.03 33.54,55.82 34.3,55.06 34.3,54.85 34.15,54.71 33.94,54.71 33.19,55.46 32.97,55.46 32.83,55.31 32.83,55.1 33.58,54.35 33.58,54.14 33.43,53.99 33.22,53.99 32.47,54.74 32.26,54.74 32.11,54.59 32.11,54.38 32.86,53.63 32.86,53.42 32.71,53.27 32.5,53.27 31.75,54.02 31.54,54.02 31.39,53.87 31.39,53.66 32.14,52.91 32.14,52.7 31.99,52.55 31.78,52.55 31.03,53.3 30.82,53.3 30.67,53.15 30.67,52.94 31.42,52.19 31.42,51.98 31.27,51.83 31.06,51.83 30.31,52.58 30.1,52.58 29.95,52.43 29.95,52.22 30.7,51.47 30.7,51.26 30.55,51.11 30.34,51.11 29.59,51.86 29.38,51.86 29.23,51.72 29.23,51.5 29.98,50.75 29.98,50.54 29.84,50.4 29.63,50.4 28.87,51.15 28.66,51.15 28.52,51 28.52,50.79 29.27,50.04 29.27,49.83 29.12,49.68 28.91,49.68 28.16,50.43 27.95,50.43 27.09,49.57 24.65,49.57 20.03,44.94 v4(16.83,44.94)
  BOTTOM w0.13: v1(98.22,76.09) 98.72,76.59 98.72,77.3 R588.1 98.8,78.39 98.8,80.86 98.68,80.99 R574.2 98.22,81.86 97.44,82.63 U99.34
I2C_SCK_LS: length 184.7
  TOP w0.127: U16.6 28.94,22.64 v1(28.5,22.2)
  L03_SIG w0.102: v1(28.5,22.2) 28.29,22.41 28.29,22.93 29,23.64 30.65,23.64 31.8,24.79 32.83,24.79 v1(33.15,24.46) ; v1(72.56,89.99) 69.04,89.99 68.44,90.59 66.46,90.59 65.73,89.86 62.5,89.86 60.77,91.59 59,91.59 58.82,91.77 58.12,91.77 57.91,91.56 52.8,91.56 52.29,92.07 44.53,92.07 44.42,91.97 44.39,91.97 41.01,88.59 31.57,88.59 27.77,92.39 25.26,92.39 22.99,90.11 19.17,90.11 17.39,91.89 10.27,91.89 2.35,83.97 2.35,81.47 1.49,80.62 1.49,76.2 2,75.69 v8(2,75.13)
  L05_SIG w0.102: v1(33.15,24.46) 33.73,25.04 33.73,26.16 32.81,27.08 32.81,29.93 33.31,30.43 33.31,38.95 32.72,39.54 v1(32.05,39.54) 27.17,39.54 23.11,43.61 17.78,43.61 17.24,44.14 12.31,44.14 11.45,45 11.45,48.54 10,49.98 10,50.29 9.6,50.69 9.04,50.69 8.86,50.87 8.86,52.65 5.08,56.43 5.08,61.69 5.46,62.07 5.46,71.26 2.38,74.34 2.24,74.34 2,74.58 v8(2,75.13)
  BOTTOM w0.13: U43.38 68.36,90.51 68.88,89.99 v1(72.56,89.99) ; v8(2,75.13) 1.69,75.45 U14.9 ; R55.2 v1(28.5,22.2) ; U15.6 33.85,25.15 v1(33.15,24.46) ; v1(32.05,39.54) 32.26,39.75 U19.8
I2C_SDA_LS: length 174
  TOP w0.127: v1(27.61,22.2) 28.29,22.88 U16.5
  L03_SIG w0.102: v1(27.61,22.2) 27.81,22.4 27.81,23.13 28.8,24.13 30.45,24.13 31.6,25.27 32.82,25.27 v1(33.2,25.65) ; v8(1.98,73.86) 2.49,74.37 2.49,75.89 1.98,76.4 1.98,80.42 2.83,81.27 2.83,83.77 10.47,91.41 17.19,91.41 19.05,89.56 23.11,89.56 25.46,91.91 27.57,91.91 31.37,88.11 31.57,88.11 31.59,88.08 41.22,88.08 44.73,91.59 52.09,91.59 52.6,91.08 57.86,91.08 58.11,90.83 58.69,90.83 58.93,91.08 60.6,91.08 62.3,89.38 65.93,89.38 66.64,90.09 68.08,90.09 v1(68.23,89.94)
  L05_SIG w0.102: v8(1.98,73.86) 2.18,73.86 4.97,71.06 4.97,62.27 4.59,61.89 4.59,56.23 8.38,52.45 8.38,50.35 9.17,49.55 9.75,49.55 10.84,48.46 10.84,44.9 13.25,42.49 17.37,42.49 17.85,42.97 22.43,42.97 26.47,38.93 v1(32.65,38.93) 31.68,37.96 31.68,27.16 v1(33.2,25.65)
  BOTTOM w0.13: v1(68.23,89.94) 68.24,89.94 68.24,89.98 68.1,90.11 U43.39 ; R56.2 v1(27.61,22.2) ; U15.5 v1(33.2,25.65) ; U19.7 33.09,39.36 v1(32.65,38.93) ; v8(1.98,73.86) 1.69,73.57 U14.8
JTAG_TCK_C2M: length 136.3
  TOP w0.127: J3.6 v1(39.4,1.82)
  TOP w0.13: JA1.A25 v4(16.83,57.01)
  L03_SIG w0.102: v1(39.4,1.82) 38.74,1.17 30.35,1.17 28.8,2.72 14.84,2.72 8.56,9.01 8.56,19.76 7.24,21.08 7.24,29.47 4.62,32.09 4.62,33.83 5.02,34.23 5.02,35.17 5,35.19 5,36.75 5.58,37.33 5.58,39.7 5.89,40.01 5.89,41.68 6.37,42.16 7.25,42.16 7.84,42.75 7.84,44.31 7.24,44.91 7.24,47.78 7.83,48.38 7.83,52.71 9.09,53.97 9.78,53.97 10.99,55.18 12.13,55.18 12.28,55.33 12.28,55.35 12.49,55.56 13.62,55.56 13.97,55.91 16.15,55.91 16.41,56.17 16.41,56.59 v4(16.83,57.01)
  L05_SIG w0.102: v1(39.54,32.17) 38.87,31.49 38.87,25.25 40.2,23.92 40.2,21.46 41.49,20.18 41.49,18.35 41.16,18.02 39.62,18.02 36.9,15.3 36.9,1.64 37.2,1.34 38.91,1.34 v1(39.4,1.82)
  BOTTOM w0.13: v4(16.83,57.01) 17.66,56.18 R264.1 ; R66.2 v1(39.54,32.17)
JTAG_TDI_C2M: length 121.1
  TOP w0.127: J3.10 v1(35.4,1.82)
  TOP w0.13: JA1.A24 v4(16.83,56.37)
  L03_SIG w0.102: v1(35.4,1.82) 30.82,1.82 29.24,3.4 15.11,3.4 9.18,9.34 9.18,19.97 7.72,21.43 7.72,29.67 6.33,31.06 6.33,38.21 7.22,39.1 7.22,41.44 8.32,42.55 8.32,44.51 7.72,45.11 7.72,47.54 10.51,50.33 10.51,53.53 11.41,54.43 12.16,54.43 12.51,54.08 14.49,54.08 14.68,54.27 14.68,55.38 14.95,55.65 16.5,55.65 16.83,55.98 v4(16.83,56.37)
  L05_SIG w0.102: v1(35.4,1.82) 35.94,2.37 35.94,23.64 35.2,24.38 35.2,26.36 36.37,27.53 36.37,30.52 v1(37.35,31.5)
  BOTTOM w0.13: U22.14 38.39,30.23 37.35,31.28 v1(37.35,31.5)
JTAG_TDO_M2C: length 125.3
  TOP w0.127: J3.8 v1(37.4,1.82)
  TOP w0.13: U25.4 v1(50.57,24.75) ; JA1.A23 v4(16,55.17)
  L03_SIG w0.102: v1(37.4,1.82) 35.3,3.92 15.64,3.92 9.79,9.76 9.79,20.18 8.2,21.77 8.2,29.87 7.02,31.05 7.02,36.97 8.02,37.97 8.02,40.4 8.36,40.73 8.36,41.76 8.8,42.2 8.8,44.71 8.2,45.31 8.2,47.34 11.12,50.26 11.12,53.38 11.68,53.95 12.01,53.95 12.08,53.88 14.65,53.88 14.84,54.07 16.23,54.07 16.43,54.27 16.43,54.75 v4(16,55.17)
  L05_SIG w0.102: v1(37.4,1.82) 38.12,2.55 38.12,15.38 39.75,17.01 42.16,17.01 45.87,20.71 45.87,26.18 47.14,27.45 50.09,27.45 51.1,26.44 51.1,25.27 v1(50.57,24.75)
JTAG_TMS_C2M: length 123.6
  TOP w0.127: J3.4 v1(41.4,1.82)
  TOP w0.13: JA1.A22 v4(16.83,55.1) ; U25.5 49.96,25.15 v1(50.62,25.81)
  L03_SIG w0.102: v4(16.83,55.1) 17.23,54.7 17.23,54.1 16.83,53.69 14.89,53.69 14.73,53.53 14.73,52.34 14.39,51.99 12.06,51.99 11.68,51.61 11.68,50.14 8.82,47.28 8.82,45.37 9.32,44.87 9.32,38.53 7.51,36.72 7.51,31.25 8.69,30.07 8.69,22.16 10.36,20.49 10.36,10.07 15.96,4.47 38.75,4.47 v1(41.4,1.82)
  L05_SIG w0.102: v1(41.4,1.82) 40.56,2.66 40.56,15.64 41.17,16.25 42.35,16.25 46.35,20.25 46.35,25.65 47.51,26.82 49.6,26.82 v1(50.62,25.81)
JTAG_VCCO_ON: length 32
  L03_SIG w0.102: v1(37.35,26.67) 37.74,26.28 37.74,24.41 36.88,23.54 36.88,20.36 40.44,16.79 42.07,16.79 43.58,15.27 44.41,15.27 46.66,13.02 48.71,13.02 49.08,12.66 50.91,12.66 51.72,13.47 v1(51.72,15.96)
  BOTTOM w0.13: R241.1 37.35,25.92 37.35,25.92 v1(37.35,26.67) 37.67,26.67 37.99,26.99 U22.8 ; U24.21 v1(51.72,15.96)
LS_OE_B: length 26
  TOP w0.127: v1(53.32,21) R233.2 53.32,20.11 Q12.3
  TOP w0.13: U25.2 49.17,24 49.73,23.44 v1(49.73,22.5)
  L03_SIG w0.102: v1(53.32,21) 51.81,22.5 v1(49.73,22.5) 49.73,24.26 48.87,25.12 48.87,26.55 43.97,31.44 v1(40.27,31.44)
  BOTTOM w0.13: v1(40.27,31.44) 40.27,29.59 39.93,29.26 U22.1
MIO24_I2C_SCK: length 42.7
  TOP w0.127: U16.3 v1(28.94,28.79)
  TOP w0.13: JA1.C26 v4(13.46,57.07)
  L10_SIG w0.102: v4(13.46,57.07) 13.04,57.5 12.29,57.5 11.02,56.23 11.02,50.56 11.7,49.88 13.69,49.88 13.87,49.7 13.87,46.63 14.55,45.94 14.55,44.83 14.83,44.55 17.19,44.55 18.42,43.31 18.42,40.06 28.57,29.91 28.57,29.16 v1(28.94,28.79)
MIO25_I2C_SDA: length 43.3
  TOP w0.127: v1(27.89,28.76) 28.29,28.36 U16.4
  TOP w0.13: JA1.C27 v4(14.29,58.28)
  L10_SIG w0.102: v1(27.89,28.76) 28.09,28.95 28.09,29.71 17.9,39.9 17.9,43.15 16.89,44.17 14.5,44.17 14.14,44.52 14.14,45.74 13.64,46.25 13.28,46.25 13.07,46.46 13.07,47.8 10.53,50.34 10.53,56.43 12.04,57.93 13.94,57.93 v4(14.29,58.28)
MIO26: length 72.3
  TOP w0.13: JA1.D28 v4(12.65,58.37)
  L10_SIG w0.102: v4(12.65,58.37) 13.05,58.77 13.05,61.16 13.36,61.46 17.44,61.46 19.44,59.46 19.44,58.15 23.77,53.82 37.21,53.82 43.09,47.94 43.09,29.28 43.74,28.63 43.74,25.65 42.36,24.28 41.21,24.28 J1.1
  BOTTOM w0.13: J1.1 38.88,23.8 38.37,24.3 R45.2
MIO27_NC: length 0.4
  TOP w0.13: JA1.D29 v4(12.65,59)
MIO28_NC: length 0.6
  TOP w0.13: JA1.D30 v4(13.47,60.21)
MIO29_NC: length 0.4
  TOP w0.13: JA1.C30 v4(14.29,60.18)
MIO30_NC: length 0.4
  TOP w0.13: JA1.C31 v4(14.29,60.82)
MIO31: length 7.2
  TOP w0.13: v1(8.92,62.66) 8.3,63.27 TP37.1 ; JA1.C32 v4(13.46,60.88)
  BOTTOM w0.13: v1(8.92,62.66) 9.67,62.66 10.15,62.18 R263.1 12.71,61.64 v4(13.46,60.88)
MIO32_NC: length 0.4
  TOP w0.13: JA1.A31 v4(16.83,60.82)
MIO33_NC: length 0.6
  TOP w0.13: JA1.A32 v4(16,60.88)
MIO34_NC: length 0.4
  TOP w0.13: JA1.B38 v4(15.19,64.72)
MIO35: length 80
  TOP w0.13: JA1.B28 v4(15.19,58.37)
  L05_SIG w0.102: v1(36.23,54.28) 36.23,54.35 35.45,55.13 20.4,55.13 17.65,57.88 15.67,57.88 v4(15.19,58.37) 14.7,57.88 12.54,57.88 12.2,58.22 12.2,65.82 10.67,67.35 10.67,81.8 9.43,83.03 9.43,85.91 4.61,90.72 3.65,90.72 3.15,90.22 v1(3.15,89.77)
  L12_SIG w0.102: v1(36.23,54.28) 36.24,54.28 36.86,53.66 36.86,46.91 35.66,45.71 35.66,43.77 36.06,43.38 v1(36.75,43.38)
  BOTTOM w0.13: R530.2 37.04,43.09 v1(36.75,43.38) 36.75,43.08 36.34,42.67 U19.26 ; U13.7 v1(3.15,89.77)
MIO36: length 54.7
  TOP w0.13: JA1.B29 v4(15.19,59)
  L10_SIG w0.102: v1(42.11,26.08) 41.14,27.05 41.14,30.55 41.53,30.93 41.53,46.99 37.55,50.96 34.82,50.96 34.2,51.57 24.5,51.57 17.83,58.25 17.83,58.85 17.23,59.45 15.63,59.45 v4(15.19,59)
  BOTTOM w0.13: U64.4 v1(42.11,26.08)
MIO37: length 54
  TOP w0.13: JA1.B30 v4(16.01,60.21)
  L10_SIG w0.102: v4(16.01,60.21) 16.43,59.78 17.5,59.78 18.28,59 18.28,58.62 24.24,52.66 36.82,52.66 42.67,46.82 42.67,27.74 v1(42.07,27.14)
  BOTTOM w0.13: U64.5 42.73,26.48 v1(42.07,27.14)
MIO38: length 99.8
  TOP w0.13: v1(69.01,84.67) 67.7,85.97 67.7,86.25 67.07,86.88 66.99,86.88 66.29,87.58 65.58,87.58 65.03,88.13 U98.38 ; JA1.B32 v4(15.19,60.91)
  L03_SIG w0.102: v1(69.01,84.67) 69.78,84.67 69.95,84.5 69.95,83.38 69.67,83.1 68.91,83.1 68.3,82.49 66.95,82.49 66.82,82.37 66.82,82.09 64.19,79.46 63.46,79.46 62.89,78.89 61.44,78.89 60.19,80.14 59.42,80.14 58.86,79.58 53.56,79.58 52.91,78.94 49.3,78.94 47.55,77.19 47.55,75.69 43.28,71.42 43.01,71.42 42.69,71.1 42.69,70.53 42.52,70.36 42.31,70.36 42.15,70.52 41.97,70.52 41.79,70.34 41.79,70.16 41.95,70 41.95,69.79 41.8,69.64 41.59,69.64 40.95,70.28 40.74,70.28 40.59,70.13 40.59,69.92 41.23,69.28 41.23,69.07 41.08,68.92 40.87,68.92 40.23,69.56 40.02,69.56 39.87,69.41 39.87,69.2 40.51,68.56 40.51,68.35 40.37,68.2 40.16,68.2 39.52,68.84 39.3,68.84 39.16,68.7 39.16,68.49 39.8,67.84 39.8,67.63 39.65,67.49 39.44,67.49 38.8,68.13 38.59,68.13 38.44,67.98 38.44,67.77 39.08,67.13 39.08,66.92 38.93,66.77 38.72,66.77 38.08,67.41 37.87,67.41 37.72,67.26 37.72,67.05 38.36,66.41 38.36,66.2 38.21,66.05 38,66.05 37.36,66.69 37.15,66.69 37,66.54 37,66.33 37.64,65.69 37.64,65.48 37.49,65.33 37.28,65.33 36.64,65.97 36.43,65.97 36.28,65.82 36.28,65.61 36.92,64.97 36.92,64.76 36.77,64.61 36.56,64.61 35.92,65.25 35.71,65.25 35.56,65.1 35.56,64.89 36.2,64.25 36.2,64.04 36.06,63.89 35.85,63.89 35.2,64.53 34.99,64.53 34.85,64.39 34.85,64.17 35.49,63.53 35.49,63.32 35.34,63.18 35.13,63.18 34.49,63.82 34.28,63.82 34.13,63.67 34.13,63.46 34.77,62.82 34.77,62.61 34.62,62.46 34.41,62.46 33.77,63.1 33.56,63.1 33.41,62.95 33.41,62.74 34.05,62.1 34.05,61.89 33.44,61.28 26.13,61.28 24.52,59.66 19.48,59.66 17.86,61.28 15.61,61.28 15.24,60.91 v4(15.19,60.91)
MIO39: length 76.3
  TOP w0.13: v1(69.01,85.68) 68.31,86.38 68.02,86.38 67.09,87.31 66.93,87.31 66.36,87.88 65.82,87.88 65.53,88.17 U98.39 ; JA1.B33 v4(16.01,62.11)
  L05_SIG w0.102: v1(69.01,85.68) 68.49,85.17 68.49,84.57 68.11,84.19 59.38,84.19 59.22,84.34 59.22,85.05 59.02,85.25 58.54,85.25 58.37,85.07 58.37,84.84 58.19,84.66 57.94,84.66 57.76,84.84 57.76,85.07 57.58,85.25 56.1,85.25 50.66,79.81 49.96,79.81 48.78,78.63 47.8,78.63 42.23,78.63 41.23,77.64 41.23,76.9 38.2,73.87 38.2,71.2 37.88,70.87 37.67,70.87 37.47,71.07 37.26,71.07 37.11,70.92 37.11,70.71 37.31,70.51 37.31,70.3 37.16,70.15 36.95,70.15 36.75,70.35 36.54,70.35 36.39,70.2 36.39,69.99 36.59,69.8 36.59,69.58 36.44,69.44 36.23,69.44 36.04,69.63 35.83,69.63 35.68,69.48 35.68,69.27 35.87,69.08 35.87,68.87 35.72,68.72 35.51,68.72 35.32,68.91 35.11,68.91 34.96,68.76 34.96,68.55 35.15,68.36 35.15,68.15 29.42,62.41 19.23,62.41 18.89,62.07 17.45,62.07 17.08,61.7 16.42,61.7 v4(16.01,62.11)
MIO40: length 99.5
  TOP w0.13: v1(67.15,88.36) 66.63,88.88 U98.1 ; JA1.B34 v4(15.19,62.18)
  L05_SIG w0.102: v4(15.19,62.18) 15.59,62.59 15.59,63.3 15.79,63.5 17.17,63.5 18.32,64.65 26.01,64.65 26.27,64.9 26.27,65.11 25.6,65.78 25.6,65.99 25.75,66.14 25.96,66.14 26.63,65.47 26.84,65.47 26.99,65.62 26.99,65.83 26.32,66.5 26.32,66.71 26.47,66.86 26.68,66.86 27.35,66.19 27.56,66.19 27.71,66.34 27.71,66.55 27.04,67.22 27.04,67.43 27.19,67.57 27.4,67.57 28.07,66.91 28.28,66.91 28.42,67.06 28.42,67.27 27.76,67.93 27.76,68.14 27.91,68.29 28.12,68.29 28.78,67.63 28.99,67.63 29.14,67.78 29.14,67.99 28.48,68.65 28.48,68.86 28.63,69.01 28.84,69.01 29.5,68.35 29.71,68.35 29.86,68.49 29.86,68.71 29.2,69.37 29.2,69.58 29.34,69.73 29.56,69.73 30.22,69.06 30.43,69.06 30.58,69.21 30.58,69.42 29.91,70.09 29.91,70.3 30.06,70.45 30.27,70.45 30.94,69.78 31.15,69.78 31.3,69.93 31.3,70.14 30.63,70.81 30.63,71.02 30.78,71.17 30.99,71.17 31.66,70.5 31.87,70.5 32.02,70.65 32.02,70.86 31.35,71.53 31.35,71.74 31.5,71.89 31.71,71.89 32.38,71.22 32.59,71.22 32.74,71.37 32.74,71.58 32.07,72.24 32.07,72.46 32.22,72.6 32.43,72.6 33.09,71.94 33.31,71.94 33.45,72.09 33.45,72.3 32.79,72.96 32.79,73.17 32.94,73.32 33.15,73.32 33.81,72.66 34.02,72.66 34.17,72.81 34.17,73.02 33.51,73.68 33.51,73.89 33.66,74.04 33.87,74.04 34.53,73.37 34.74,73.37 34.89,73.52 34.89,73.73 34.22,74.4 34.22,74.61 34.37,74.76 34.58,74.76 35.25,74.09 35.46,74.09 35.61,74.24 35.61,74.45 34.94,75.12 34.94,75.33 35.09,75.48 35.3,75.48 35.97,74.81 36.18,74.81 36.33,74.96 36.33,75.17 35.66,75.84 35.66,76.05 35.81,76.2 36.02,76.2 36.69,75.53 36.9,75.53 37.4,76.03 37.4,76.23 36.65,76.98 36.65,77.5 36.99,77.84 37.65,77.84 38.27,78.46 38.43,78.46 39.4,79.43 40.83,79.43 41.34,79.95 41.34,80.71 41.75,81.12 45.31,81.12 45.56,80.87 48.73,80.87 50.06,82.19 50.99,82.19 55.37,86.57 55.37,86.99 56.16,87.78 56.63,87.78 56.85,88 59.78,88 60.14,88.36 v1(67.15,88.36)
MIO41: length 98
  TOP w0.13: U98.2 67.22,89.76 68.39,88.59 71.8,88.59 72.34,88.06 v1(72.34,84.7) ; JA1.A34 v4(16.83,62.72)
  L05_SIG w0.102: v1(72.34,84.7) 72.28,84.7 70.78,86.2 68.63,86.2 67.27,84.84 64.92,84.84 64.64,85.12 60.04,85.12 59.42,85.73 55.9,85.73 50.5,80.34 49.68,80.34 48.5,79.16 42.08,79.16 40.46,77.55 40.46,77.03 35.88,72.45 35.88,72.24 36.47,71.66 36.47,71.45 36.32,71.3 36.11,71.3 35.53,71.88 35.31,71.88 35.17,71.73 35.17,71.52 35.75,70.94 35.75,70.73 35.6,70.58 35.39,70.58 34.81,71.16 34.6,71.16 34.45,71.02 34.45,70.81 35.03,70.22 35.03,70.01 34.88,69.86 34.67,69.86 34.09,70.45 33.88,70.45 33.73,70.3 33.73,70.09 34.32,69.5 34.32,69.29 34.17,69.14 33.96,69.14 33.37,69.73 33.16,69.73 33.01,69.58 33.01,69.37 33.6,68.78 33.6,68.57 33.45,68.42 33.24,68.42 32.65,69.01 32.44,69.01 32.29,68.86 32.29,68.65 32.88,68.06 32.88,67.85 32.73,67.7 32.52,67.7 31.93,68.29 31.72,68.29 31.57,68.14 31.57,67.93 32.16,67.35 32.16,67.14 32.01,66.99 31.8,66.99 31.21,67.57 31,67.57 30.86,67.42 30.86,67.21 31.44,66.63 31.44,66.42 31.29,66.27 31.08,66.27 30.5,66.85 30.29,66.85 30.14,66.71 30.14,66.49 30.72,65.91 30.72,65.7 30.57,65.55 30.36,65.55 29.78,66.14 29.57,66.14 29.42,65.99 29.42,65.78 30,65.19 30,64.98 29.86,64.83 29.65,64.83 29.06,65.42 28.85,65.42 28.7,65.27 28.7,65.06 29.29,64.47 29.29,64.26 29.14,64.11 28.93,64.11 28.34,64.7 28.13,64.7 26.39,62.95 18.27,62.95 18.03,62.72 v4(16.83,62.72)
MIO42: length 75.7
  TOP w0.13: JA1.A35 v4(16,62.79) ; v1(72.61,88.57) 72.28,88.9 68.52,88.9 67.16,90.26 U98.3
  L05_SIG w0.102: v1(72.61,88.57) 71.47,88.57 70.29,87.38 67.78,87.38 67.53,87.63 61.16,87.63 60.49,86.95 56.73,86.95 56,86.23 55.71,86.23 50.36,80.88 49.46,80.88 48.27,79.69 41.83,79.69 40.43,78.29 39.33,78.29 38.85,77.82 38.32,77.82 37.84,77.34 37.84,75.74 26.23,64.13 18.54,64.13 17.62,63.21 16.42,63.21 v4(16,62.79)
MIO43: length 99.5
  TOP w0.13: U98.37 64.53,88.15 65.38,87.3 66.21,87.3 66.57,86.94 66.57,85.7 66.8,85.47 67.19,85.47 v1(69.01,83.65) ; JA1.A36 v4(16.83,63.99)
  L03_SIG w0.102: v1(69.01,83.65) 67.84,84.82 57.91,84.82 57.4,84.31 56.35,84.31 55.65,85.01 v1(52.98,85.01)
  L05_SIG w0.102: v1(52.98,85.01) 50.89,82.92 50.1,82.92 49.51,82.33 46.95,82.33 46.5,82.79 44.91,82.79 44.76,82.64 44.76,81.6 44.61,81.45 44.4,81.45 44.25,81.6 44.25,82.64 44.1,82.79 43.89,82.79 43.74,82.64 43.74,81.6 43.6,81.45 43.38,81.45 43.24,81.6 43.24,82.64 43.09,82.79 42.88,82.79 42.73,82.64 42.73,81.6 42.58,81.45 42.37,81.45 42.22,81.6 42.22,82.64 42.07,82.79 41.86,82.79 41.71,82.64 41.71,81.6 41.56,81.45 41.35,81.45 41.2,81.6 41.2,82.64 41.06,82.79 40.83,82.79 40.36,82.32 40.36,80.67 40.23,80.54 38.95,80.54 38.8,80.39 38.8,79.75 38.65,79.6 38.44,79.6 38.3,79.75 38.3,80.39 38.15,80.54 37.92,80.54 37.72,80.34 37.72,79.86 36.79,78.94 36.79,78.53 35.97,77.7 35.97,77.49 36.17,77.3 36.17,77.09 36.02,76.94 35.81,76.94 35.61,77.13 35.4,77.13 35.25,76.99 35.25,76.78 35.45,76.58 35.45,76.37 35.3,76.22 35.09,76.22 34.89,76.42 34.68,76.42 34.53,76.27 34.53,76.06 34.73,75.86 34.73,75.65 34.58,75.5 34.37,75.5 34.17,75.7 33.96,75.7 33.81,75.55 33.81,75.34 34.01,75.14 34.01,74.93 33.86,74.78 33.65,74.78 33.45,74.98 33.24,74.98 33.1,74.83 33.1,74.62 33.29,74.42 33.29,74.21 33.14,74.06 32.93,74.06 32.74,74.26 32.53,74.26 32.38,74.11 32.38,73.9 32.57,73.7 32.57,73.49 32.43,73.34 32.22,73.34 32.02,73.54 31.81,73.54 31.66,73.39 31.66,73.18 31.86,72.99 31.86,72.78 31.71,72.63 31.5,72.63 31.3,72.82 31.09,72.82 30.94,72.68 30.94,72.46 31.14,72.27 31.14,72.06 30.99,71.91 30.78,71.91 30.58,72.11 30.37,72.11 30.22,71.96 30.22,71.75 30.42,71.55 30.42,71.34 30.27,71.19 30.06,71.19 29.86,71.39 29.65,71.39 29.5,71.24 29.5,71.03 29.7,70.83 29.7,70.62 29.55,70.47 29.34,70.47 29.14,70.67 28.93,70.67 28.78,70.52 28.78,70.31 28.98,70.11 28.98,69.9 28.83,69.75 28.62,69.75 28.43,69.95 28.21,69.95 28.07,69.8 28.07,69.59 28.26,69.39 28.26,69.18 28.12,69.03 27.9,69.03 27.71,69.23 27.5,69.23 27.35,69.08 27.35,68.87 27.55,68.67 27.55,68.46 27.4,68.32 27.19,68.32 26.99,68.51 26.78,68.51 26.63,68.36 26.63,68.15 26.83,67.96 26.83,67.75 26.68,67.6 26.47,67.6 26.27,67.8 26.06,67.8 25.91,67.65 25.91,67.44 26.11,67.24 26.11,67.03 25.96,66.88 25.75,66.88 25.55,67.08 25.34,67.08 25.19,66.93 25.19,66.72 25.39,66.52 25.39,66.31 25.24,66.16 25.03,66.16 24.83,66.36 24.62,66.36 24.47,66.21 24.47,66 24.67,65.8 24.67,65.59 24.52,65.44 24.31,65.44 24.11,65.64 23.9,65.64 23.44,65.18 20.15,65.18 20,65.33 20,66.01 19.85,66.16 19.64,66.16 19.49,66.01 19.49,65.33 19.34,65.18 19.13,65.18 18.98,65.33 18.98,66.01 18.83,66.16 18.62,66.16 18.47,66.01 18.47,65.33 18.33,65.18 18.01,65.18 v4(16.83,63.99)
MIO44: length 94.3
  TOP w0.13: U98.34 63.03,87.74 62.8,87.51 62.8,86.27 61.73,85.19 61.73,83.31 61.26,82.84 60.57,82.84 60.56,82.83 R547.2 R558.1 58.65,82.83 58.65,82.84 57.31,82.84 v1(56.33,81.86) ; JA1.D32 v4(12.65,60.91)
  L05_SIG w0.102: v4(12.65,60.91) 13.06,60.5 13.06,59.81 13.48,59.39 15.39,59.39 15.42,59.37 17.16,59.37 20.67,55.85 23.18,55.85 23.32,56 23.32,56.87 23.47,57.02 23.68,57.02 23.83,56.87 23.83,56 23.98,55.85 24.19,55.85 24.34,56 24.34,56.87 24.49,57.02 24.7,57.02 24.85,56.87 24.85,56 25,55.85 25.21,55.85 25.36,56 25.36,56.87 25.51,57.02 25.72,57.02 25.86,56.87 25.86,56 26.01,55.85 26.22,55.85 26.37,56 26.37,56.87 26.52,57.02 26.73,57.02 26.88,56.87 26.88,56 27.03,55.85 27.24,55.85 27.39,56 27.39,56.87 27.54,57.02 27.75,57.02 27.9,56.87 27.9,56 28.05,55.85 28.26,55.85 28.4,56 28.4,56.87 28.55,57.02 28.76,57.02 28.91,56.87 28.91,56 29.06,55.85 29.27,55.85 29.42,56 29.42,56.87 29.57,57.02 29.78,57.02 29.93,56.87 29.93,56 30.08,55.85 30.29,55.85 30.44,56 30.44,56.87 30.59,57.02 30.8,57.02 30.94,56.87 30.94,56 31.09,55.85 31.3,55.85 31.45,56 31.45,56.87 31.6,57.02 31.81,57.02 31.96,56.87 31.96,56 32.11,55.85 32.32,55.85 32.47,56 32.47,56.87 32.62,57.02 32.83,57.02 32.98,56.87 32.98,56 33.13,55.85 33.34,55.85 33.48,56 33.48,56.87 33.63,57.02 34.59,57.02 36.34,58.77 36.34,61.48 43.63,68.77 44.52,68.77 47.56,71.82 47.56,73.27 48.3,74.02 50.16,74.02 54.03,77.89 55.46,77.89 56.72,79.14 56.72,81.48 v1(56.33,81.86)
MIO45: length 89.5
  TOP w0.13: JA1.D33 v4(13.47,62.11) ; v1(55.11,81.76) 56.76,83.41 60.8,83.41 61.05,83.66 R545.2 R556.1 61.05,85.18 62.49,86.62 62.49,87.64 62.53,87.68 U98.33
  L05_SIG w0.102: v4(13.47,62.11) 13.47,61.92 14.1,61.29 14.48,61.29 14.74,61.03 14.74,60.13 14.97,59.9 15.61,59.9 15.72,59.79 17.27,59.79 17.52,60.04 18.23,60.04 19,59.28 21.31,59.28 22.63,57.96 23.3,57.96 23.45,58.11 23.45,58.75 23.6,58.9 23.81,58.9 23.96,58.75 23.96,58.11 24.1,57.96 24.31,57.96 24.46,58.11 24.46,58.75 24.61,58.9 24.82,58.9 24.97,58.75 24.97,58.11 25.12,57.96 25.33,57.96 25.48,58.11 25.48,58.75 25.63,58.9 25.84,58.9 25.99,58.75 25.99,58.11 26.14,57.96 26.35,57.96 26.5,58.11 26.5,58.75 26.64,58.9 26.85,58.9 27,58.75 27,58.11 27.15,57.96 27.36,57.96 27.51,58.11 27.51,58.75 27.66,58.9 27.87,58.9 28.02,58.75 28.02,58.11 28.17,57.96 28.38,57.96 28.53,58.11 28.53,58.75 28.68,58.9 28.89,58.9 29.04,58.75 29.04,58.11 29.18,57.96 29.39,57.96 29.54,58.11 29.54,58.75 29.69,58.9 29.9,58.9 30.05,58.75 30.05,58.11 30.2,57.96 30.41,57.96 30.56,58.11 30.56,58.75 30.71,58.9 30.92,58.9 31.07,58.75 31.07,58.11 31.22,57.96 31.43,57.96 31.58,58.11 31.58,58.75 31.72,58.9 31.93,58.9 32.08,58.75 32.08,58.11 32.23,57.96 32.44,57.96 32.59,58.11 32.59,58.75 32.74,58.9 32.95,58.9 33.1,58.75 33.1,58.11 33.25,57.96 33.65,57.96 35.33,59.63 35.33,62.3 43.7,70.67 43.7,71.13 47.37,74.8 47.37,75.6 47.49,75.72 47.98,75.72 48.1,75.84 48.1,76.01 47.98,76.13 47.49,76.13 47.37,76.24 47.37,76.55 48.01,77.19 50.47,77.19 52.14,78.86 52.8,78.86 53.03,79.09 53.03,79.6 53.2,79.78 53.46,79.78 54.03,79.21 54.28,79.21 54.46,79.38 54.46,79.64 53.89,80.21 53.89,80.46 54.07,80.64 54.32,80.64 54.62,80.34 54.87,80.34 55.11,80.59 v1(55.11,81.76)
MIO46: length 71.6
  TOP w0.13: v1(55.83,83.46) 55.83,85.54 56.14,85.86 R555.1 R544.2 60.09,87.04 60.51,87.04 61.06,87.59 61.6,87.59 62.03,88.02 U98.32 ; JA1.D34 v4(12.65,62.18)
  L05_SIG w0.102: v4(12.65,62.18) 12.65,61.72 12.87,61.49 13.43,61.49 13.88,61.04 13.88,59.98 14.22,59.64 15.5,59.64 15.57,59.57 17.61,59.57 18.46,58.72 21.08,58.72 22.37,57.43 34.01,57.43 35.91,59.33 35.91,61.99 44.16,70.23 44.91,70.23 46.88,72.2 46.88,73.35 49.92,76.39 51.14,76.39 52.52,77.77 52.7,77.77 53.46,78.53 54.58,78.53 55.83,79.78 v1(55.83,83.46)
